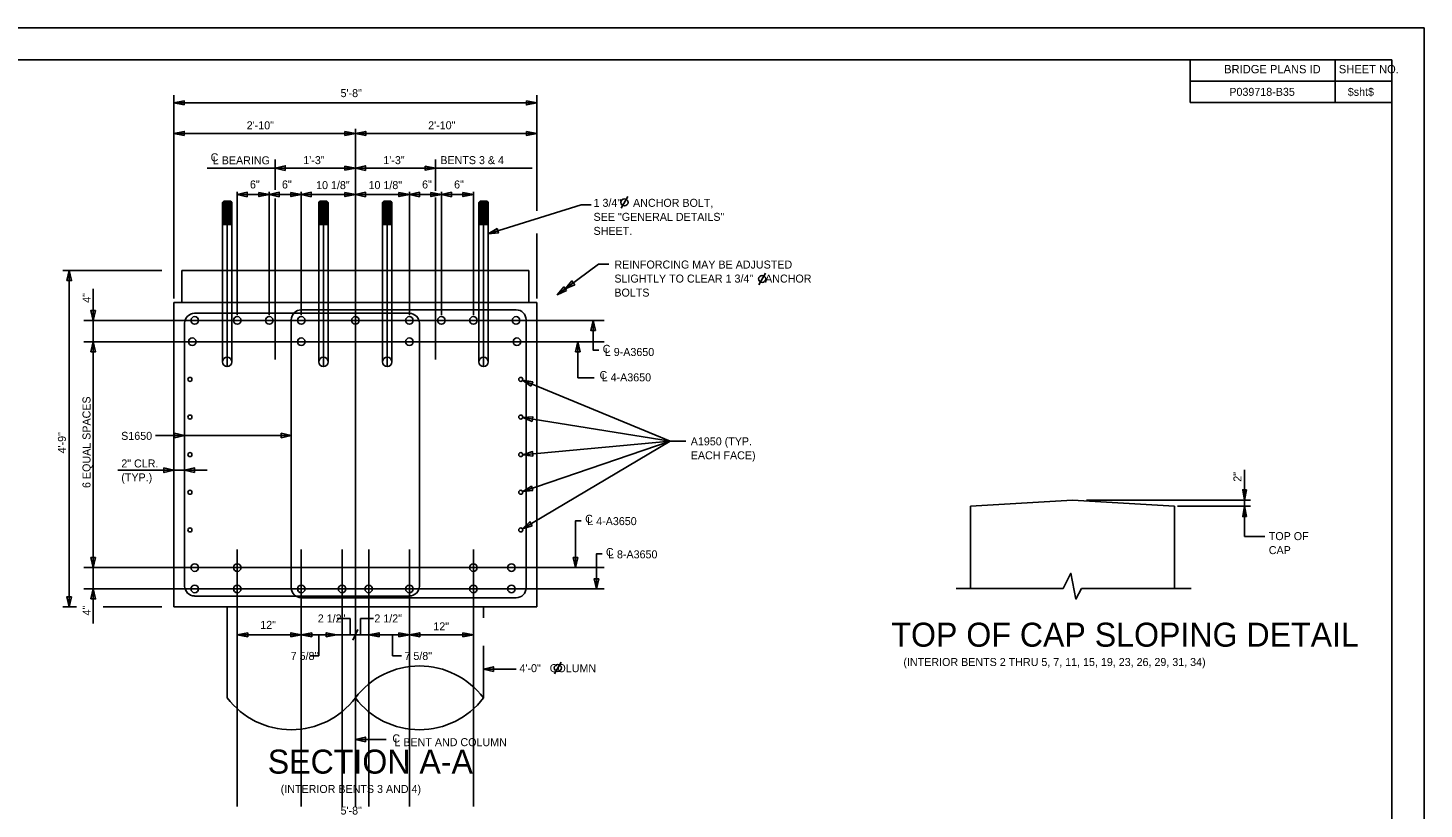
# Model space of a CAD drawing. Extents: x -133.1 to -97, y -1.7 to 20.3.
# Drawn here: x -118.94 to -97.14, y 8.11 to 20.31 of the extents above; entities that cross this region are included whole.
import ezdxf

# ---------------------------------------------------------------- set-up
doc = ezdxf.new("R2010")
doc.units = 0
for name, color, linetype in [('BR_AUTO DIMENSION', 7, 'Continuous'), ('BR_BORDER LINES', 7, 'Continuous'), ('BR_CENTER LINES', 7, 'Continuous'), ('BR_CONCRETE', 7, 'Continuous'), ('BR_REBAR', 7, 'Continuous'), ('BR_STRUCTURAL STEEL', 7, 'Continuous'), ('BR_TEXT', 7, 'Continuous'), ('Default', 7, 'Continuous'), ('Level 31', 7, 'Continuous')]:
    doc.layers.add(name, color=color, linetype=linetype)

msp = doc.modelspace()

# ---------------------------------------------------------------- linework, layer by layer
at = {"layer": 'BR_AUTO DIMENSION'}
for p, q in [((-116.664, 16.08), (-116.664, 19.256)), ((-110.998, 17.454), (-110.998, 19.256)), ((-116.664, 19.138), (-110.998, 19.138)), ((-116.664, 18.662), (-113.831, 18.662)), ((-113.831, 17.979), (-113.831, 18.735)), ((-110.998, 18.662), (-113.831, 18.662)), ((-116.145, 18.12), (-112.581, 18.12)), ((-112.581, 18.12), (-111.071, 18.12)), ((-115.675, 15.824), (-115.675, 17.748)), ((-115.675, 17.707), (-111.987, 17.707)), ((-115.175, 15.824), (-115.175, 17.748)), ((-114.675, 15.824), (-114.675, 17.748)), ((-112.987, 15.824), (-112.987, 17.748)), ((-112.487, 15.824), (-112.487, 17.748)), ((-111.987, 15.824), (-111.987, 17.748)), ((-111.756, 17.094), (-110.303, 17.547)), ((-110.303, 17.547), (-110.149, 17.547)), ((-110.998, 16.08), (-110.998, 17.097)), ((-116.851, 16.519), (-118.397, 16.519)), ((-118.299, 16.519), (-118.299, 11.268)), ((-117.924, 16.232), (-117.924, 11.006)), ((-110.355, 15.407), (-110.355, 14.845)), ((-110.355, 14.845), (-110.104, 14.845)), ((-108.917, 13.856), (-111.219, 14.806)), ((-108.917, 13.856), (-111.218, 14.222)), ((-114.831, 13.943), (-116.954, 13.943)), ((-108.917, 13.856), (-111.221, 12.483)), ((-108.917, 13.856), (-111.216, 13.64)), ((-116.146, 13.399), (-117.538, 13.399)), ((-99.943, 13.406), (-99.943, 12.365)), ((-102.412, 12.932), (-99.85, 12.932)), ((-100.991, 12.839), (-99.85, 12.839)), ((-99.63, 12.365), (-99.943, 12.365)), ((-118.186, 11.268), (-118.397, 11.268)), ((-116.851, 11.268), (-117.77, 11.268)), ((-115.675, 10.698), (-115.675, 11.249)), ((-114.675, 10.692), (-114.675, 11.244)), ((-114.039, 11.146), (-114.039, 11.246)), ((-113.623, 11.146), (-113.623, 11.246)), ((-112.987, 10.692), (-112.987, 11.244)), ((-111.987, 10.698), (-111.987, 11.249)), ((-113.91, 11.084), (-114.116, 11.084)), ((-114.039, 10.698), (-114.039, 11.016)), ((-113.91, 10.83), (-113.91, 11.084)), ((-113.868, 10.747), (-113.794, 10.912)), ((-113.752, 10.83), (-113.752, 11.084)), ((-113.752, 11.084), (-113.545, 11.084)), ((-113.623, 10.698), (-113.623, 11.016)), ((-111.987, 10.83), (-115.675, 10.83)), ((-114.399, 10.83), (-114.399, 10.498)), ((-113.253, 10.83), (-113.253, 10.498)), ((-114.399, 10.498), (-114.542, 10.498)), ((-113.253, 10.498), (-113.109, 10.498)), ((-111.831, 10.293), (-111.319, 10.293)), ((-113.831, 9.194), (-113.348, 9.194))]:
    msp.add_line(p, q, dxfattribs=at)
for points in [[(-116.502, 19.106), (-116.664, 19.138), (-116.502, 19.169)], [(-111.16, 19.169), (-110.998, 19.138), (-111.16, 19.106)], [(-116.502, 18.631), (-116.664, 18.662), (-116.502, 18.693)], [(-113.993, 18.693), (-113.831, 18.662), (-113.993, 18.631)], [(-113.668, 18.631), (-113.831, 18.662), (-113.668, 18.693)], [(-111.16, 18.693), (-110.998, 18.662), (-111.16, 18.631)], [(-114.925, 18.084), (-115.081, 18.12), (-114.925, 18.156)], [(-113.993, 18.151), (-113.831, 18.12), (-113.993, 18.089)], [(-113.675, 18.084), (-113.831, 18.12), (-113.675, 18.156)], [(-112.743, 18.151), (-112.581, 18.12), (-112.743, 18.089)], [(-115.519, 17.671), (-115.675, 17.707), (-115.519, 17.743)], [(-115.337, 17.738), (-115.175, 17.707), (-115.337, 17.675)], [(-115.019, 17.671), (-115.175, 17.707), (-115.019, 17.743)], [(-114.837, 17.738), (-114.675, 17.707), (-114.837, 17.675)], [(-114.519, 17.671), (-114.675, 17.707), (-114.519, 17.743)], [(-113.993, 17.738), (-113.831, 17.707), (-113.993, 17.675)], [(-113.675, 17.671), (-113.831, 17.707), (-113.675, 17.743)], [(-113.15, 17.738), (-112.987, 17.707), (-113.15, 17.675)], [(-112.831, 17.671), (-112.987, 17.707), (-112.831, 17.743)], [(-112.65, 17.738), (-112.487, 17.707), (-112.65, 17.675)], [(-112.331, 17.671), (-112.487, 17.707), (-112.331, 17.743)], [(-112.15, 17.738), (-111.987, 17.707), (-112.15, 17.675)], [(-111.618, 17.175), (-111.756, 17.094), (-111.596, 17.106)], [(-118.335, 16.363), (-118.299, 16.519), (-118.263, 16.363)], [(-110.406, 16.298), (-110.552, 16.234), (-110.449, 16.356)], [(-110.531, 16.205), (-110.677, 16.14), (-110.574, 16.263)], [(-117.888, 15.896), (-117.924, 15.74), (-117.96, 15.896)], [(-110.082, 15.584), (-110.118, 15.74), (-110.154, 15.584)], [(-117.96, 15.251), (-117.924, 15.407), (-117.888, 15.251)], [(-110.319, 15.251), (-110.355, 15.407), (-110.391, 15.251)], [(-111.088, 14.714), (-111.219, 14.806), (-111.061, 14.78)], [(-111.069, 14.161), (-111.218, 14.222), (-111.058, 14.233)], [(-116.653, 13.979), (-116.498, 13.943), (-116.653, 13.907)], [(-114.987, 13.979), (-114.831, 13.943), (-114.987, 13.907)], [(-111.058, 13.619), (-111.216, 13.64), (-111.064, 13.691)], [(-116.82, 13.435), (-116.664, 13.399), (-116.82, 13.363)], [(-116.342, 13.363), (-116.498, 13.399), (-116.342, 13.435)], [(-111.059, 13.082), (-111.218, 13.065), (-111.082, 13.15)], [(-99.912, 13.095), (-99.943, 12.932), (-99.974, 13.095)], [(-99.912, 12.676), (-99.943, 12.839), (-99.974, 12.676)], [(-111.069, 12.532), (-111.221, 12.483), (-111.106, 12.594)], [(-117.888, 12.034), (-117.924, 11.878), (-117.96, 12.034)], [(-110.355, 12.034), (-110.391, 11.878), (-110.427, 12.034)], [(-110.031, 11.701), (-110.067, 11.545), (-110.103, 11.701)], [(-118.263, 11.424), (-118.299, 11.268), (-118.335, 11.424)], [(-117.96, 11.389), (-117.924, 11.545), (-117.888, 11.389)], [(-115.512, 10.861), (-115.675, 10.83), (-115.512, 10.799)], [(-114.837, 10.799), (-114.675, 10.83), (-114.837, 10.861)], [(-114.512, 10.861), (-114.675, 10.83), (-114.512, 10.799)], [(-114.285, 10.799), (-114.123, 10.83), (-114.285, 10.861)], [(-113.46, 10.799), (-113.623, 10.83), (-113.46, 10.861)], [(-113.15, 10.861), (-112.987, 10.83), (-113.15, 10.799)], [(-112.825, 10.799), (-112.987, 10.83), (-112.825, 10.861)], [(-112.15, 10.861), (-111.987, 10.83), (-112.15, 10.799)], [(-111.675, 10.257), (-111.831, 10.293), (-111.675, 10.329)], [(-113.675, 9.158), (-113.831, 9.194), (-113.675, 9.23)]]:
    msp.add_lwpolyline(points, close=True, dxfattribs=at)
for points in [[(-110.677, 16.14), (-110.036, 16.619), (-109.871, 16.619)], [(-110.118, 15.74), (-110.118, 15.277), (-110.03, 15.277)], [(-111.218, 13.065), (-108.917, 13.856), (-108.669, 13.856)], [(-110.391, 11.878), (-110.391, 12.611), (-110.303, 12.611)], [(-110.067, 11.545), (-110.067, 12.091), (-109.979, 12.091)]]:
    msp.add_lwpolyline(points, dxfattribs=at)
at = {"layer": 'BR_BORDER LINES'}
for p, q in [((-97.642, 19.809), (-131.308, 19.809)), ((-100.794, 19.142), (-100.794, 19.809)), ((-98.528, 19.142), (-98.528, 19.809)), ((-97.642, -1.191), (-97.642, 19.809)), ((-100.794, 19.479), (-97.642, 19.479)), ((-98.528, 19.479), (-97.642, 19.479)), ((-97.642, 19.142), (-100.794, 19.142))]:
    msp.add_line(p, q, dxfattribs=at)
at = {"layer": 'BR_CENTER LINES'}
for p, q in [((-115.081, 18.255), (-115.081, 17.782)), ((-113.831, 18.192), (-113.831, 9.079)), ((-112.581, 18.255), (-112.581, 17.763)), ((-115.081, 17.645), (-115.081, 15.128)), ((-112.581, 17.66), (-112.581, 15.128)), ((-115.833, 15.019), (-115.833, 17.391)), ((-114.329, 15.019), (-114.329, 17.391)), ((-113.333, 15.019), (-113.333, 17.391)), ((-111.829, 15.019), (-111.829, 17.391)), ((-118.072, 15.74), (-109.944, 15.74)), ((-118.072, 15.407), (-109.944, 15.407)), ((-118.072, 11.878), (-109.944, 11.878)), ((-118.072, 11.545), (-109.944, 11.545))]:
    msp.add_line(p, q, dxfattribs=at)
at = {"layer": 'BR_CONCRETE'}
for p, q in [((-116.539, 16.519), (-116.539, 16.018)), ((-116.539, 16.519), (-111.123, 16.519)), ((-111.123, 16.519), (-111.123, 16.018)), ((-116.664, 16.018), (-116.664, 11.268)), ((-116.664, 16.018), (-110.998, 16.018)), ((-110.998, 16.018), (-110.998, 11.268)), ((-104.226, 12.839), (-102.632, 12.932)), ((-101.039, 12.839), (-102.632, 12.932)), ((-104.226, 12.839), (-104.226, 11.55)), ((-101.039, 12.839), (-101.039, 11.55)), ((-116.664, 11.268), (-110.998, 11.268)), ((-115.831, 11.268), (-115.831, 9.843)), ((-111.831, 11.268), (-111.831, 11.095)), ((-111.831, 10.656), (-111.831, 9.843))]:
    msp.add_line(p, q, dxfattribs=at)
for centre, start, end in [((-112.831, 9.09), 37.0023, 142.9977), ((-114.831, 10.597), 217.0023, 322.9977), ((-112.831, 10.597), 217.0023, 322.9977)]:
    msp.add_arc(centre, 1.252, start, end, dxfattribs=at)
at = {"layer": 'BR_REBAR'}
for p, q in [((-116.344, 15.851), (-112.987, 15.851)), ((-114.831, 15.749), (-114.831, 11.563)), ((-111.318, 15.905), (-114.675, 15.905)), ((-111.164, 15.747), (-111.164, 11.561)), ((-116.498, 15.697), (-116.498, 11.588)), ((-112.831, 15.695), (-112.831, 11.591)), ((-116.344, 11.434), (-112.981, 11.434)), ((-111.318, 11.407), (-114.685, 11.407))]:
    msp.add_line(p, q, dxfattribs=at)
for centre, radius in [((-116.339, 15.74), 0.0588), ((-115.675, 15.74), 0.0588), ((-115.175, 15.74), 0.0588), ((-114.675, 15.74), 0.0588), ((-113.831, 15.74), 0.0588), ((-112.987, 15.74), 0.0588), ((-112.487, 15.74), 0.0588), ((-111.987, 15.74), 0.0588), ((-111.322, 15.74), 0.0588), ((-116.378, 15.407), 0.0588), ((-114.675, 15.407), 0.0588), ((-112.987, 15.407), 0.0588), ((-111.307, 15.407), 0.0588), ((-116.414, 14.819), 0.0313), ((-111.248, 14.819), 0.0313), ((-116.414, 14.231), 0.0313), ((-111.248, 14.231), 0.0313), ((-116.414, 13.643), 0.0313), ((-111.248, 13.643), 0.0313), ((-116.414, 13.055), 0.0313), ((-111.248, 13.055), 0.0313), ((-116.414, 12.467), 0.0313), ((-111.248, 12.467), 0.0313), ((-116.339, 11.878), 0.0588), ((-115.675, 11.878), 0.0588), ((-111.987, 11.878), 0.0588), ((-111.393, 11.878), 0.0588), ((-116.339, 11.545), 0.0588), ((-115.675, 11.545), 0.0588), ((-114.675, 11.545), 0.0588), ((-114.039, 11.545), 0.0588), ((-113.623, 11.545), 0.0588), ((-112.987, 11.545), 0.0588), ((-111.987, 11.545), 0.0588), ((-111.393, 11.545), 0.0588)]:
    msp.add_circle(centre, radius, dxfattribs=at)
for centre, start, end in [((-116.341, 15.695), 91.025, 178.975), ((-114.675, 15.749), 90, 180), ((-112.987, 15.695), 0, 90), ((-111.32, 15.749), 1.025, 88.975), ((-116.341, 11.591), 181.025, 268.975), ((-114.675, 11.563), 180, 270), ((-112.987, 11.591), 270, 0), ((-111.32, 11.563), 271.025, 358.975)]:
    msp.add_arc(centre, 0.156, start, end, dxfattribs=at)
at = {"layer": 'BR_STRUCTURAL STEEL'}
for p, q in [((-115.887, 17.602), (-115.906, 17.584)), ((-115.76, 17.584), (-115.906, 17.584)), ((-115.906, 17.584), (-115.906, 16.519)), ((-115.76, 17.566), (-115.906, 17.566)), ((-115.76, 17.548), (-115.906, 17.548)), ((-115.76, 17.529), (-115.906, 17.529)), ((-115.76, 17.511), (-115.906, 17.511)), ((-115.76, 17.493), (-115.906, 17.493)), ((-115.76, 17.475), (-115.906, 17.475)), ((-115.76, 17.456), (-115.906, 17.456)), ((-115.778, 17.602), (-115.887, 17.602)), ((-115.76, 17.584), (-115.778, 17.602)), ((-115.76, 17.584), (-115.76, 16.519)), ((-114.384, 17.602), (-114.402, 17.584)), ((-114.256, 17.584), (-114.402, 17.584)), ((-114.402, 17.584), (-114.402, 16.519)), ((-114.256, 17.566), (-114.402, 17.566)), ((-114.256, 17.548), (-114.402, 17.548)), ((-114.256, 17.529), (-114.402, 17.529)), ((-114.256, 17.511), (-114.402, 17.511)), ((-114.256, 17.493), (-114.402, 17.493)), ((-114.256, 17.475), (-114.402, 17.475)), ((-114.256, 17.456), (-114.402, 17.456)), ((-114.274, 17.602), (-114.384, 17.602)), ((-114.256, 17.584), (-114.274, 17.602)), ((-114.256, 17.584), (-114.256, 16.519)), ((-113.387, 17.602), (-113.406, 17.584)), ((-113.26, 17.584), (-113.406, 17.584)), ((-113.406, 17.584), (-113.406, 16.519)), ((-113.26, 17.566), (-113.406, 17.566)), ((-113.26, 17.548), (-113.406, 17.548)), ((-113.26, 17.529), (-113.406, 17.529)), ((-113.26, 17.511), (-113.406, 17.511)), ((-113.26, 17.493), (-113.406, 17.493)), ((-113.26, 17.475), (-113.406, 17.475)), ((-113.26, 17.456), (-113.406, 17.456)), ((-113.278, 17.602), (-113.387, 17.602)), ((-113.26, 17.584), (-113.278, 17.602)), ((-113.26, 17.584), (-113.26, 16.519)), ((-111.884, 17.602), (-111.902, 17.584)), ((-111.756, 17.584), (-111.902, 17.584)), ((-111.902, 17.584), (-111.902, 16.519)), ((-111.756, 17.566), (-111.902, 17.566)), ((-111.756, 17.548), (-111.902, 17.548)), ((-111.756, 17.529), (-111.902, 17.529)), ((-111.756, 17.511), (-111.902, 17.511)), ((-111.756, 17.493), (-111.902, 17.493)), ((-111.756, 17.475), (-111.902, 17.475)), ((-111.756, 17.456), (-111.902, 17.456)), ((-111.774, 17.602), (-111.884, 17.602)), ((-111.756, 17.584), (-111.774, 17.602)), ((-111.756, 17.584), (-111.756, 16.519)), ((-115.76, 17.438), (-115.906, 17.438)), ((-115.76, 17.42), (-115.906, 17.42)), ((-115.76, 17.402), (-115.906, 17.402)), ((-115.76, 17.383), (-115.906, 17.383)), ((-115.76, 17.365), (-115.906, 17.365)), ((-115.76, 17.347), (-115.906, 17.347)), ((-115.76, 17.329), (-115.906, 17.329)), ((-115.76, 17.311), (-115.906, 17.311)), ((-115.76, 17.292), (-115.906, 17.292)), ((-115.76, 17.274), (-115.906, 17.274)), ((-115.76, 17.256), (-115.906, 17.256)), ((-115.76, 17.238), (-115.906, 17.238)), ((-114.256, 17.438), (-114.402, 17.438)), ((-114.256, 17.42), (-114.402, 17.42)), ((-114.256, 17.402), (-114.402, 17.402)), ((-114.256, 17.383), (-114.402, 17.383)), ((-114.256, 17.365), (-114.402, 17.365)), ((-114.256, 17.347), (-114.402, 17.347)), ((-114.256, 17.329), (-114.402, 17.329)), ((-114.256, 17.311), (-114.402, 17.311)), ((-114.256, 17.292), (-114.402, 17.292)), ((-114.256, 17.274), (-114.402, 17.274)), ((-114.256, 17.256), (-114.402, 17.256)), ((-114.256, 17.238), (-114.402, 17.238)), ((-113.26, 17.438), (-113.406, 17.438)), ((-113.26, 17.42), (-113.406, 17.42)), ((-113.26, 17.402), (-113.406, 17.402)), ((-113.26, 17.383), (-113.406, 17.383)), ((-113.26, 17.365), (-113.406, 17.365)), ((-113.26, 17.347), (-113.406, 17.347)), ((-113.26, 17.329), (-113.406, 17.329)), ((-113.26, 17.311), (-113.406, 17.311)), ((-113.26, 17.292), (-113.406, 17.292)), ((-113.26, 17.274), (-113.406, 17.274)), ((-113.26, 17.256), (-113.406, 17.256)), ((-113.26, 17.238), (-113.406, 17.238)), ((-111.756, 17.438), (-111.902, 17.438)), ((-111.756, 17.42), (-111.902, 17.42)), ((-111.756, 17.402), (-111.902, 17.402)), ((-111.756, 17.383), (-111.902, 17.383)), ((-111.756, 17.365), (-111.902, 17.365)), ((-111.756, 17.347), (-111.902, 17.347)), ((-111.756, 17.329), (-111.902, 17.329)), ((-111.756, 17.311), (-111.902, 17.311)), ((-111.756, 17.292), (-111.902, 17.292)), ((-111.756, 17.274), (-111.902, 17.274)), ((-111.756, 17.256), (-111.902, 17.256)), ((-111.756, 17.238), (-111.902, 17.238)), ((-115.906, 16.519), (-115.906, 15.092)), ((-115.76, 16.519), (-115.76, 15.092)), ((-114.402, 16.519), (-114.402, 15.092)), ((-114.256, 16.519), (-114.256, 15.092)), ((-113.406, 16.519), (-113.406, 15.092)), ((-113.26, 16.519), (-113.26, 15.092)), ((-111.902, 16.519), (-111.902, 15.092)), ((-111.756, 16.519), (-111.756, 15.092))]:
    msp.add_line(p, q, dxfattribs=at)
for centre in [(-115.833, 15.092), (-114.329, 15.092), (-113.333, 15.092), (-111.829, 15.092)]:
    msp.add_circle(centre, 0.0729, dxfattribs=at)
at = {"layer": 'BR_TEXT'}
for p, q in [((-109.681, 17.493), (-109.576, 17.675)), ((-107.53, 16.297), (-107.425, 16.479)), ((-118.299, 11.268), (-118.299, 11.415)), ((-110.721, 10.22), (-110.616, 10.402))]:
    msp.add_line(p, q, dxfattribs=at)
for centre in [(-109.628, 17.584), (-107.478, 16.388), (-110.669, 10.311)]:
    msp.add_circle(centre, 0.055, dxfattribs=at)
at = {"layer": 'Default'}
for p, q in [((-104.449, 11.55), (-102.778, 11.55)), ((-102.491, 11.55), (-100.779, 11.55))]:
    msp.add_line(p, q, dxfattribs=at)
msp.add_lwpolyline([(-102.491, 11.55), (-102.579, 11.387), (-102.655, 11.789), (-102.778, 11.55)], dxfattribs=at)
at = {"layer": 'Level 31'}
for p, q in [((-115.675, 12.159), (-115.675, 8.146)), ((-114.675, 12.159), (-114.675, 8.146)), ((-114.039, 12.159), (-114.039, 8.146)), ((-113.831, 12.159), (-113.831, 8.146)), ((-113.623, 12.159), (-113.623, 8.146)), ((-112.987, 12.159), (-112.987, 8.146)), ((-111.987, 12.159), (-111.987, 8.146))]:
    msp.add_line(p, q, dxfattribs=at)
msp.add_lwpolyline([(-133.141, -1.691), (-97.141, -1.691), (-97.141, 20.309), (-133.141, 20.309)], close=True, dxfattribs=at)

# ---------------------------------------------------------------- texts
at = {"layer": 'BR_AUTO DIMENSION'}
for s, p in [('5\'-8"', (-114.062, 19.228)), ('2\'-10"', (-115.528, 18.725)), ('2\'-10"', (-112.694, 18.725)), ('TOP OF', (-99.566, 12.308)), ('CAP', (-99.566, 12.089)), ('5\'-8"', (-114.062, 8.021))]:
    msp.add_text(s, height=0.125, dxfattribs=at).set_placement(p)
msp.add_text('2"', height=0.125, rotation=90, dxfattribs=at).set_placement((-99.993, 13.22))
at = {"layer": 'BR_TEXT'}
for s, height, p in [('BRIDGE PLANS ID', 0.13, (-100.263, 19.6)), ('SHEET NO.', 0.13, (-98.472, 19.6)), ('P039718-B35', 0.125, (-100.182, 19.248)), ('$sht$', 0.125, (-98.332, 19.248)), ('2 1/2"', 0.125, (-114.418, 11.022)), ('2 1/2"', 0.125, (-113.534, 11.022)), ('TOP OF CAP SLOPING DETAIL', 0.375, (-105.46, 10.643)), ('SECTION A-A', 0.375, (-115.199, 8.66))]:
    msp.add_text(s, height=height, dxfattribs=at).set_placement(p)
for s, rotation, p in [('C', 360, (-116.091, 18.225)), ('L BEARING', 360, (-116.057, 18.178)), ('1\'-3"', 360, (-114.644, 18.181)), ('1\'-3"', 360, (-113.394, 18.181)), ('BENTS 3 & 4', 360, (-112.504, 18.181)), ('6"', 360, (-115.477, 17.801)), ('6"', 360, (-114.977, 17.801)), ('10 1/8"', 360, (-114.444, 17.791)), ('10 1/8"', 360, (-113.625, 17.791)), ('6"', 360, (-112.789, 17.801)), ('6"', 360, (-112.289, 17.801)), ('1 3/4"    ANCHOR BOLT, ', 360, (-110.111, 17.514)), ('SEE "GENERAL DETAILS"', 360, (-110.111, 17.295)), ('SHEET.', 360, (-110.111, 17.076)), ('REINFORCING MAY BE ADJUSTED', 360, (-109.786, 16.55)), ('SLIGHTLY TO CLEAR 1 3/4"    ANCHOR', 360, (-109.786, 16.331)), ('4"', 90, (-117.967, 16.015)), ('BOLTS', 360, (-109.786, 16.112)), ('C', 360, (-109.969, 15.233)), ('L 9-A3650', 360, (-109.935, 15.184)), ('C', 360, (-110.017, 14.824)), ('L 4-A3650', 360, (-109.984, 14.788)), ('6 EQUAL SPACES', 90, (-117.967, 13.122)), ('4\'-9"', 90, (-118.351, 13.662)), ('S1650', 360, (-117.488, 13.874)), ('A1950 (TYP.', 360, (-108.593, 13.788)), ('2" CLR.', 360, (-117.486, 13.443)), ('EACH FACE)', 360, (-108.593, 13.57)), ('(TYP.)', 360, (-117.486, 13.225)), ('C', 360, (-110.242, 12.578)), ('L 4-A3650', 360, (-110.209, 12.542)), ('C', 360, (-109.918, 12.059)), ('L 8-A3650', 360, (-109.885, 12.023)), ('4"', 90, (-117.967, 11.131)), ('12"', 360, (-115.316, 10.921)), ('12"', 360, (-112.613, 10.898)), ('7 5/8"', 360, (-114.841, 10.436)), ('7 5/8"', 360, (-113.064, 10.436)), ('(INTERIOR BENTS 2 THRU 5, 7, 11, 15, 19, 23, 26, 29, 31, 34)', 360, (-105.272, 10.341)), ('4\'-0"   COLUMN', 360, (-111.268, 10.245)), ('C', 360, (-113.253, 9.148)), ('L BENT AND COLUMN', 360, (-113.221, 9.089)), ('(INTERIOR BENTS 3 AND 4)', 360, (-114.997, 8.358))]:
    msp.add_text(s, height=0.125, rotation=rotation, dxfattribs=at).set_placement(p)

doc.saveas('drawing.dxf')
